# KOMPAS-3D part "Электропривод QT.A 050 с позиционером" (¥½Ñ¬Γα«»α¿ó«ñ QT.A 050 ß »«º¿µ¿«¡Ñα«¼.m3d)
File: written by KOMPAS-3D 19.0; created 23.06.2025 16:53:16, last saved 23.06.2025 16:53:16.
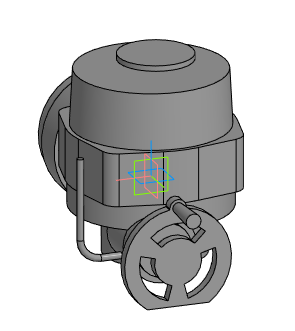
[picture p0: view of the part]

Document properties: Автор: Евгений; Полное имя файла: E:\Dendor Работа Сачек\3D для проектировщиков\3.5 Тип QT.А Электропривод\stp_Электропривод QT.A с позиционером\Электропривод QT.A 050 с позиционером.m3d

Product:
- Part/product: Электропривод QT.A 050 с позиционером

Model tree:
1. Операция без истории:1  (labels: Электропривод QT.A 050 с позиционером)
